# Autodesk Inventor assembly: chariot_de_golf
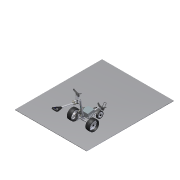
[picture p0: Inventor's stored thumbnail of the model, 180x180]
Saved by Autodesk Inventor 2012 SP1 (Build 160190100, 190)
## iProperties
Created: 2011-01
Part Number: chariot_de_golf
Document SubType Name: Assembly
Designer: eric
Norme de conversion: STEP AP214IS
Nom du fichier: chariot_de_golf.STEP
Préprocesseur: SolidWorks 2007
Postprocesseur: Build: 342, Release: 2008 SP3 - Date: Tue 05/27/2008
Unités envoyées: MILLIMETERS
Incertitude: 1e-05
Author: eric
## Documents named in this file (6)
- D:\Cours\Inventor salle SI\chariot_de_golf_2008\chariot_de_golf_trolem\chariot_de_golf.iam
- D:\Cours\Inventor salle SI\chariot_de_golf_2008\chariot_de_golf_trolem\Chassis.iam
- D:\Cours\Inventor salle SI\chariot_de_golf_2008\chariot_de_golf_trolem\essieu_avant.iam
- D:\Cours\Inventor salle SI\chariot_de_golf_2008\chariot_de_golf_trolem\essieu_arriere.iam
- D:\Cours\Inventor salle SI\chariot_de_golf_2008\chariot_de_golf_trolem\rotor moteur.iam
- D:\Cours\Inventor salle SI\chariot_de_golf_2008\chariot_de_golf_trolem\Sol.ipt
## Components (5 placed, 5 different names)
1. Chassis:1 [sub-assembly] — Logement:1, Logement:2, pilotage du moteur, Logement:3, Affleurement:2, Placage:1
2. essieu_avant:1 [sub-assembly] — Tangente:1, Logement:3, Tangente:3, Affleurement:3, Placage:1
3. essieu_arriere:1 [sub-assembly] — Logement:2, Tangente:2
4. rotor moteur:1 [sub-assembly] — Logement:1, pilotage du moteur
5. Sol:1 — Affleurement:1, Tangente:1, Tangente:2, Affleurement:2, Tangente:3, Affleurement:3
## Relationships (11: Insert 3, Flush 3, Tangent 3, Angle 1, Mate 1)
- Logement:1 [Insert]: Chassis:1 ↔ rotor moteur:1
- Logement:2 [Insert]: Chassis:1 ↔ essieu_arriere:1
- pilotage du moteur [Angle]: Chassis:1 ↔ rotor moteur:1
- Affleurement:1 [Flush]: Sol:1
- Tangente:1: essieu_avant:1 ↔ Sol:1
- Logement:3 [Insert]: Chassis:1 ↔ essieu_avant:1
- Tangente:2: essieu_arriere:1 ↔ Sol:1
- Affleurement:2 [Flush]: Chassis:1 ↔ Sol:1
- Tangente:3: essieu_avant:1 ↔ Sol:1
- Affleurement:3 [Flush]: essieu_avant:1 ↔ Sol:1
- Placage:1 [Mate]: Chassis:1 ↔ essieu_avant:1
